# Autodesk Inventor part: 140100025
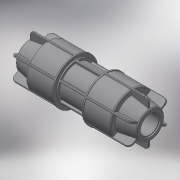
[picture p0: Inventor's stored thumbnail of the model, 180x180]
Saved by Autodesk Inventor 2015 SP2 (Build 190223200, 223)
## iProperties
Created: 2018-02
Part Number: 140100025
Material: Generic
Description: PLASSON L.14 COUPLER (SILVER) 25
Document SubType Name: Modeling
Designer: KIM
Mass: 102.105 g
Surface Area: 273.296 cm^2
Volume: 102.105 cm^3
Density: 1 g/cm^3
Appearance: Default
Author: KIM
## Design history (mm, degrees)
derived "140100.ipt"
feature "Solid1::140100.ipt"
tag "TaggingFeature1"
body "Solid1"
other parameters: "d30" = 1, "d36" = 0.98, "d65" = 48.5, "d77" = 23, "d93" = 37.5, "d95" = 14.7, "d96" = 0.98, "d97" = 27.5, "d100" = 37.5, "d102" = 37.24, "d103" = 0.98, "d107" = 62.65, "d114" = 2.5, "d115" = 1.25, "d117" = 0, "d126" = 5, "d127" = 0.5, "d129" = 360 deg, "d131" = 0.98, "d138" = 100 deg, "d139" = 42.5, "d141" = 98, "d142" = 25, "d143" = 48, "d144" = 0, "d145" = 25, "d146" = 48, "d147" = 0, "d149" = 2.5, "d150" = 1.25, "d152" = 0, "d153" = 0.5, "d155" = 360 deg, "l_" = 48, "d_" = 25, "H_" = 98
